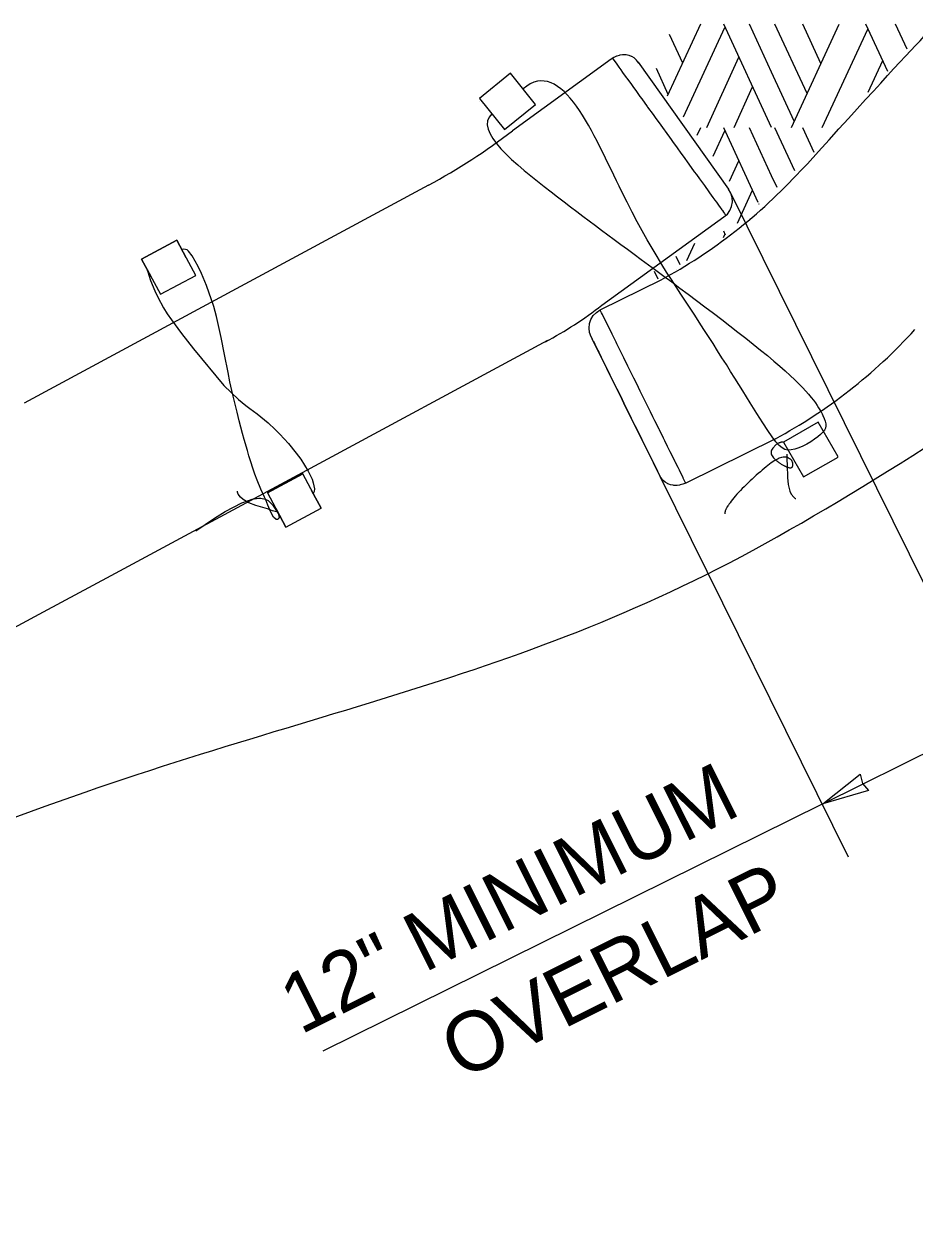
# Model space of a CAD drawing. Extents: x 99862 to 103680, y 99470 to 102076.
# Drawn here: x 100381.8 to 100622.3, y 100816.7 to 101141.7 of the extents above; entities that cross this region are included whole.
import ezdxf

# ---------------------------------------------------------------- set-up
doc = ezdxf.new("R2010")
doc.units = 0
for name, color, linetype in [('Level 10', 7, 'Continuous'), ('Level 11', 7, 'Continuous'), ('Level 15', 7, 'Continuous'), ('Level 17', 7, 'Continuous'), ('Level 20', 7, 'Continuous'), ('Level 4', 7, 'Continuous'), ('Level 6', 7, 'Continuous'), ('Level 8', 7, 'Continuous')]:
    doc.layers.add(name, color=color, linetype=linetype)

msp = doc.modelspace()

# ---------------------------------------------------------------- linework, layer by layer
at = {"layer": 'Level 10'}
msp.add_line((100557.85, 101075.37), (100557.85, 101075.37), dxfattribs=at)
at = {"layer": 'Level 11'}
for p, q in [((100555.5, 101122.29), (100564.46, 101141.7)), ((100559.79, 101116.58), (100570.95, 101140.75)), ((100583.58, 101113.76), (100570.69, 101141.61)), ((100583.58, 101128.64), (100577.61, 101141.61)), ((100593.18, 101122.93), (100584.44, 101141.61)), ((100588.94, 101113.76), (100601.83, 101141.61)), ((100596.9, 101130.97), (100592.06, 101141.61)), ((100597.25, 101113.76), (100609.62, 101140.32)), ((100614.96, 101128.86), (100609.01, 101141.61)), ((100620.19, 101134.86), (100617.06, 101141.61)), ((100559.61, 101131.06), (100556.04, 101138.85)), ((100566.1, 101113.76), (100574.75, 101132.7)), ((100609.64, 101123.31), (100613.6, 101131.84)), ((100555.72, 101122.67), (100552.5, 101129.66)), ((100589.72, 101115.49), (100583.58, 101128.64)), ((100573.46, 101113.76), (100578.47, 101124.74)), ((100563.5, 101111.67), (100564.46, 101113.76)), ((100567.8, 101105.99), (100570.95, 101112.8)), ((100580.01, 101093.53), (100570.69, 101113.67)), ((100583.58, 101100.69), (100577.61, 101113.67)), ((100589.87, 101102.07), (100584.44, 101113.67)), ((100595.08, 101107.03), (100592.06, 101113.67)), ((100572.23, 101099.23), (100574.75, 101104.76)), ((100585.07, 101097.5), (100583.58, 101100.69)), ((100574.42, 101087.93), (100578.47, 101096.8)), ((100580.28, 101092.95), (100580.18, 101093.15)), ((100571.17, 101084.67), (100570.69, 101085.72)), ((100560.76, 101077.79), (100562.92, 101082.48)), ((100570.59, 101084.08), (100570.95, 101084.86)), ((100558.93, 101076.65), (100557.88, 101078.94)), ((100552.95, 101072.77), (100552.01, 101074.82))]:
    msp.add_line(p, q, dxfattribs=at)
at = {"layer": 'Level 15'}
msp.add_lwpolyline([(100597.44, 100931.19), (100607.51, 100939.12), (100608.12, 100936.65), (100609.76, 100934.72)], close=True, dxfattribs=at)
at = {"layer": 'Level 17'}
for points in [[(99945.11, 101052.79), (100070.18, 101065.89), (100261.73, 101178.58), (100444.52, 101199.27), (100595.15, 101324.54), (100692.49, 101369.86)], [(100013.36, 100816.66), (100170.82, 100823.55), (100379.05, 100946.05), (100561.83, 100966.73), (100712.46, 101092.01), (100809.8, 101137.32)]]:
    msp.add_open_spline(points, degree=3, dxfattribs=at)
at = {"layer": 'Level 20'}
for p, q in [((100650.06, 100939.36), (100572.6, 101096.01)), ((100604.35, 100916.75), (100553.53, 101019.52)), ((100597.26, 100931.09), (100642.97, 100953.7)), ((100597.26, 100931.09), (100462.44, 100864.42))]:
    msp.add_line(p, q, dxfattribs=at)
at = {"layer": 'Level 4'}
for points in [[(100428.18, 101004.84), (100433.2, 101008.29), (100436.03, 101010.03), (100440.56, 101012.39), (100442.33, 101013.07), (100443.35, 101013.37), (100445.04, 101013.65), (100445.73, 101013.65), (100446.86, 101013.43), (100447.69, 101013), (100448.8, 101011.86), (100449.96, 101010.26), (100450.4, 101009.51), (100450.62, 101008.49), (100450.39, 101008.06), (100450.19, 101007.94), (100449.82, 101007.95), (100449.13, 101008.52), (100448.47, 101009.7), (100448.13, 101010.48), (100447.58, 101011.8), (100447.01, 101013.2), (100446.71, 101013.9), (100445.73, 101016.06), (100444.71, 101018.52), (100444.11, 101020.13), (100443.44, 101022.08), (100443.07, 101023.22), (100442.48, 101025.12), (100442.07, 101026.51), (100441.21, 101029.54), (100440.76, 101031.16), (100439.87, 101034.55), (100439.28, 101036.88), (100438.14, 101041.59), (100437.36, 101045.08), (100436.83, 101047.61), (100435.87, 101052.45), (100434.97, 101057.01), (100433.7, 101062.69), (100432.97, 101065.39), (100431.05, 101071.05), (100429.67, 101074.33), (100428.77, 101076.23), (100427.15, 101079.1), (100426.19, 101080.33), (100425.76, 101080.68), (100424.94, 101080.93), (100424.35, 101080.82), (100424.34, 101080.81)], [(100415.05, 101075.3), (100415.04, 101075.24), (100415.23, 101074.46), (100415.41, 101073.91), (100415.92, 101072.42), (100417.03, 101069.64), (100417.84, 101067.94), (100419.43, 101065.05), (100420.43, 101063.45), (100421.57, 101061.77), (100424.28, 101058.09), (100427.55, 101053.95), (100435.69, 101044.09)], [(100435.69, 101044.09), (100439.66, 101040.32), (100441.63, 101038.69), (100442.74, 101037.85), (100444.71, 101036.42), (100447.69, 101033.99), (100449.6, 101032.21), (100450.84, 101030.98), (100453.16, 101028.43), (100455.25, 101025.85), (100456.48, 101024.16), (100458.49, 101020.95), (100459.52, 101018.79), (100459.86, 101017.82), (100460.17, 101016.16), (100460.12, 101015.48), (100459.86, 101014.89)], [(100587.69, 101025.57), (100587.7, 101024.03), (100587.81, 101022.67), (100587.87, 101019.29), (100588.05, 101017.36), (100588.52, 101015.56), (100588.89, 101014.78), (100589.57, 101013.94), (100589.99, 101013.61), (100590.14, 101013.55)], [(100450.3, 101009.86), (100448.82, 101010.28), (100447.53, 101010.75), (100444.3, 101011.71), (100442.48, 101012.41), (100440.88, 101013.34), (100440.23, 101013.9), (100439.59, 101014.78), (100439.4, 101015.28), (100439.36, 101015.53)]]:
    msp.add_lwpolyline(points, dxfattribs=at)
for points, degree in [([(100508.1, 101117.39), (100502.96, 101112.98), (100525.9, 101094.57), (100549.16, 101077.66), (100591.79, 101045.88), (100598.56, 101034.68), (100598.71, 101031.45), (100587.7, 101024.8), (100583.89, 101029.39), (100564.13, 101061.75), (100544.06, 101090.52), (100527.03, 101133.21), (100516.51, 101124.17)], 3), ([(100586.83, 101028.81), (100585.09, 101028.81), (100582.57, 101025.26), (100589.17, 101020.97), (100589.51, 101024.12), (100585.35, 101025.4), (100570.95, 101011.89), (100570.95, 101009.44)], 2)]:
    msp.add_open_spline(points, degree=degree, dxfattribs=at)
at = {"layer": 'Level 6'}
for p, q in [((100513.12, 101128.38), (100504.71, 101121.6)), ((100519.9, 101119.97), (100513.12, 101128.38)), ((100504.68, 101120.77), (100504.68, 101120.77)), ((100504.71, 101121.6), (100511.49, 101113.19)), ((100511.49, 101113.19), (100519.9, 101119.97)), ((100413.49, 101078.2), (100422.99, 101083.32)), ((100423, 101083.31), (100413.49, 101078.19)), ((100423, 101083.31), (100422.99, 101083.32)), ((100422.99, 101083.32), (100425.55, 101078.58)), ((100423, 101083.31), (100423, 101083.31)), ((100428.11, 101073.82), (100423, 101083.31)), ((100413.49, 101078.2), (100413.49, 101078.19)), ((100416.04, 101073.45), (100413.49, 101078.2)), ((100413.49, 101078.19), (100413.49, 101078.19)), ((100413.49, 101078.19), (100418.6, 101068.7)), ((100418.6, 101068.7), (100428.11, 101073.82)), ((100428.11, 101073.82), (100428.11, 101073.82)), ((100418.6, 101068.7), (100418.6, 101068.7)), ((100596.21, 101034.16), (100586.83, 101028.81)), ((100601.56, 101024.79), (100596.21, 101034.16)), ((100586.83, 101028.81), (100592.19, 101019.43)), ((100592.19, 101019.43), (100601.57, 101024.78)), ((100447.48, 101015.09), (100456.99, 101020.21)), ((100459.4, 101015.74), (100461.95, 101011)), ((100452.44, 101005.88), (100449.89, 101010.62)), ((100452.44, 101005.88), (100461.95, 101011.01))]:
    msp.add_line(p, q, dxfattribs=at)
for points in [[(100425.55, 101078.58), (100425.55, 101078.58), (100423, 101083.31)], [(100423, 101083.31), (100423, 101083.31), (100423, 101083.31)], [(100413.49, 101078.19), (100416.04, 101073.45), (100416.04, 101073.45)], [(100413.49, 101078.19), (100413.49, 101078.19), (100413.49, 101078.19)], [(100447.48, 101015.09), (100452.44, 101005.88), (100452.44, 101005.88), (100461.95, 101011), (100461.95, 101011.01), (100456.99, 101020.21), (100447.48, 101015.09)], [(100461.95, 101011), (100461.95, 101011), (100456.99, 101020.21), (100456.99, 101020.21)], [(100447.48, 101015.09), (100447.48, 101015.09), (100452.44, 101005.88), (100452.44, 101005.88)], [(100461.95, 101011), (100461.95, 101011), (100459.4, 101015.74)], [(100449.89, 101010.62), (100452.44, 101005.88), (100452.44, 101005.88)]]:
    msp.add_lwpolyline(points, dxfattribs=at)
at = {"layer": 'Level 8'}
for p, q in [((100540.29, 101132.2), (100513.66, 101112.87)), ((100540.97, 101132.63), (100540.29, 101132.2)), ((100541.34, 101132.8), (100540.97, 101132.63)), ((100541.7, 101132.96), (100541.34, 101132.8)), ((100541.86, 101133.02), (100541.7, 101132.96)), ((100542.46, 101133.19), (100541.86, 101133.02)), ((100542.62, 101133.23), (100542.46, 101133.19)), ((100543.39, 101133.34), (100542.62, 101133.23)), ((100543.54, 101133.35), (100543.39, 101133.34)), ((100543.61, 101133.35), (100543.54, 101133.35)), ((100544.3, 101133.32), (100543.61, 101133.35)), ((100544.73, 101133.24), (100544.3, 101133.32)), ((100545.03, 101133.19), (100544.73, 101133.24)), ((100545.17, 101133.15), (100545.03, 101133.19)), ((100545.77, 101132.92), (100545.17, 101133.15)), ((100545.85, 101132.88), (100545.77, 101132.92)), ((100546.46, 101132.52), (100545.85, 101132.88)), ((100546.58, 101132.43), (100546.46, 101132.52)), ((100546.66, 101132.35), (100546.58, 101132.43)), ((100547.1, 101131.95), (100546.66, 101132.35)), ((100547.39, 101131.59), (100547.1, 101131.95)), ((100547.75, 101131.09), (100547.39, 101131.59)), ((100547.57, 101131.34), (100572, 101097.06)), ((100537.59, 101051.75), (100538.32, 101050.27)), ((100538.32, 101050.27), (100539.11, 101048.66)), ((100539.11, 101048.66), (100539.97, 101046.94)), ((100539.97, 101046.94), (100540.87, 101045.12)), ((100540.87, 101045.12), (100541.8, 101043.22)), ((100541.8, 101043.22), (100542.77, 101041.27)), ((100542.77, 101041.27), (100543.73, 101039.34)), ((100543.73, 101039.34), (100543.75, 101039.28)), ((100543.75, 101039.28), (100544.74, 101037.28)), ((100545.73, 101035.28), (100546.71, 101033.31)), ((100546.71, 101033.31), (100547.66, 101031.39)), ((100547.66, 101031.39), (100548.57, 101029.54)), ((100548.57, 101029.54), (100550.26, 101026.13)), ((100550.26, 101026.13), (100551.01, 101024.61)), ((100551.01, 101024.61), (100551.7, 101023.22)), ((100551.7, 101023.22), (100552.82, 101020.94)), ((100552.82, 101020.94), (100553.25, 101020.07)), ((100553.25, 101020.07), (100553.53, 101019.52))]:
    msp.add_line(p, q, dxfattribs=at)
for points in [[(100540.63, 101132.41), (100540.8, 101132.18), (100541.51, 101131.19), (100541.61, 101131.06), (100542.37, 101130), (100542.88, 101129.3), (100543.37, 101128.62), (100544.38, 101127.22), (100544.5, 101127.05), (100545.75, 101125.33), (100546.13, 101124.8), (100547.09, 101123.46), (100548.06, 101122.12), (100548.53, 101121.47), (100550.04, 101119.38), (100550.14, 101119.24), (100551.61, 101117.21), (100552.34, 101116.2), (100553.22, 101114.99), (100554.59, 101113.08), (100554.85, 101112.73), (100556.48, 101110.46), (100556.86, 101109.94), (100558.11, 101108.21), (100559.1, 101106.84), (100559.7, 101106), (100561.25, 101103.86), (100562.74, 101101.8), (100563.3, 101101.02), (100564.14, 101099.86), (100565.18, 101098.42), (100565.45, 101098.04), (100566.66, 101096.37), (100566.85, 101096.1), (100567.74, 101094.87), (100568.28, 101094.12), (100568.69, 101093.55), (100569.47, 101092.48), (100569.5, 101092.44), (100570.16, 101091.53), (100570.33, 101091.29), (100570.65, 101090.84), (100570.9, 101090.5), (100570.99, 101090.37), (100571.15, 101090.14)], [(100591.4, 101102.07), (100593.26, 101103.95)], [(100490.99, 101098.19), (100431.04, 101065.9), (100381.77, 101039.36)], [(100571.68, 101090.34), (100572.37, 101091.33), (100572.82, 101092.45), (100573.02, 101093.64), (100572.94, 101094.85), (100572.6, 101096.01), (100572, 101097.06)], [(100537.77, 101065.74), (100571.68, 101090.34)], [(100536.3, 101063.83), (100537.32, 101064.48), (100553.94, 101072.7)], [(100534.87, 101057.25), (100534.46, 101058.39), (100534.31, 101059.59), (100534.43, 101060.79), (100534.82, 101061.93), (100535.45, 101062.96), (100536.3, 101063.83)], [(100560.43, 101017.75), (100560.3, 101018), (100559.76, 101019.09), (100559.69, 101019.25), (100559.11, 101020.41), (100558.73, 101021.19), (100558.35, 101021.94), (100557.59, 101023.49), (100557.5, 101023.67), (100556.56, 101025.58), (100556.26, 101026.17), (100555.53, 101027.64), (100554.8, 101029.13), (100554.45, 101029.84), (100553.3, 101032.15), (100553.23, 101032.31), (100552.12, 101034.55), (100551.56, 101035.67), (100550.9, 101037.02), (100549.86, 101039.12), (100549.66, 101039.51), (100548.43, 101042.02), (100548.14, 101042.6), (100547.2, 101044.5), (100546.44, 101046.02), (100545.99, 101046.95), (100544.82, 101049.32), (100543.69, 101051.59), (100543.26, 101052.45), (100542.63, 101053.74), (100541.84, 101055.33), (100541.63, 101055.75), (100540.72, 101057.6), (100540.57, 101057.9), (100539.9, 101059.26), (100539.49, 101060.09), (100539.18, 101060.71), (100538.59, 101061.9), (100538.57, 101061.95), (100538.07, 101062.95), (100537.94, 101063.22), (100537.69, 101063.72), (100537.51, 101064.09), (100537.44, 101064.23), (100537.32, 101064.48)], [(100405.27, 100992.78), (100455.77, 101019.98), (100523.18, 101056.29)], [(100534.87, 101057.25), (100534.87, 101057.25), (100534.97, 101057.05)], [(100584.63, 101029.72), (100560.43, 101017.75), (100559.68, 101017.44), (100559.3, 101017.33), (100558.91, 101017.23), (100558.75, 101017.2), (100558.12, 101017.13), (100557.96, 101017.11), (100557.19, 101017.13), (100557.03, 101017.15), (100556.96, 101017.16), (100556.28, 101017.3), (100555.88, 101017.45), (100555.59, 101017.55), (100555.46, 101017.62), (100554.91, 101017.95), (100554.83, 101017.99), (100554.29, 101018.45), (100554.19, 101018.56), (100554.12, 101018.65), (100553.75, 101019.12), (100553.53, 101019.52), (100553.25, 101020.07), (100552.82, 101020.94), (100552.3, 101022), (100551.7, 101023.22), (100551.01, 101024.61), (100550.26, 101026.13), (100549.44, 101027.78), (100548.57, 101029.54), (100547.66, 101031.39), (100546.71, 101033.31), (100545.73, 101035.28), (100544.74, 101037.28), (100543.75, 101039.28), (100542.77, 101041.27), (100541.8, 101043.22), (100540.87, 101045.12), (100539.97, 101046.94), (100539.11, 101048.66), (100538.32, 101050.27), (100537.59, 101051.75), (100536.93, 101053.07), (100536.36, 101054.24), (100535.87, 101055.23), (100535.47, 101056.03), (100535.17, 101056.64), (100534.97, 101057.05), (100534.87, 101057.25)], [(100534.97, 101057.05), (100534.97, 101057.04), (100535.17, 101056.64)], [(100535.17, 101056.64), (100535.18, 101056.62), (100535.47, 101056.03)], [(100535.47, 101056.03), (100535.48, 101056.01), (100535.88, 101055.2), (100536.36, 101054.24)], [(100536.36, 101054.24), (100536.37, 101054.2), (100536.93, 101053.07)], [(100536.93, 101053.07), (100536.95, 101053.03), (100537.47, 101051.99), (100537.59, 101051.75)], [(100544.74, 101037.28), (100545.18, 101036.4), (100545.73, 101035.28)], [(100280.84, 100925.75), (100387.03, 100982.95), (100405.27, 100992.78)]]:
    msp.add_lwpolyline(points, dxfattribs=at)
for centre, radius, start, end in [((100411.91, 101245.16), 166.89, 298.2841, 307.5677), ((100845.63, 100620.24), 540, 119.7533593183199, 119.75339310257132), ((100471.66, 101151.15), 108, 298.1264, 307.7418)]:
    msp.add_arc(centre, radius, start, end, dxfattribs=at)
for centre, major_axis, ratio, start_param, end_param in [((100491.07, 101210.15), (0, 153.46), 0.921041, 3.601009, 3.930938), ((100521.98, 101167.27), (0, -153.45), 0.921099, 0.459273, 0.789201)]:
    msp.add_ellipse(centre, major_axis=major_axis, ratio=ratio, start_param=start_param, end_param=end_param, dxfattribs=at)
msp.add_open_spline([(100593.26, 101103.95), (100626.21, 101140.48), (100634.79, 101148.14), (100650.95, 101162.23), (100734.03, 101204.14), (100767.56, 101221.06)], degree=3, dxfattribs=at)

# ---------------------------------------------------------------- texts
at = {"layer": 'Level 20'}
for s, p in [('12" MINIMUM', (100456.39, 100868.71)), ('OVERLAP', (100499.73, 100856.41))]:
    msp.add_text(s, height=16, rotation=26.5934, dxfattribs=at).set_placement(p)

doc.saveas('drawing.dxf')
